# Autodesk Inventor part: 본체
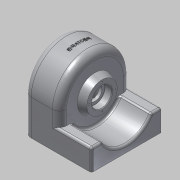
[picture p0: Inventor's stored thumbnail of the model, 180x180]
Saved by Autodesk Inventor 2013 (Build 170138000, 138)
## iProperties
Created: 2015-02
Part Number: 본체
Material: 알루미늄 6061
Document SubType Name: Modeling
Designer: Administrator
Density: 1 g/cm^3
Author: Administrator
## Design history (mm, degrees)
sketch "스케치1"
  geometry: L1 (-50, -25)-(50, -25); L2 (50, -25)-(50, 25); L3 (50, 25)-(-50, 25); L4 (-50, 25)-(-50, -25); L5 (-50, -25)-(50, 25); L6 (50, -25)-(-50, 25); A1 r 50 centre (0, 25) between (50, 25) and (-50, 25); 1 further point
  constraints: 12 end point, 3 midpoint, 2 parallel, 2 point on circle, 1 centre point, 1 horizontal, 1 perpendicular
  dimensions: "d0" = 100 distance of L1.start L1.end; "d2" = 50 distance of L3.end L1.start
extrude "돌출2" new body sketch "스케치1" distance "d7" = 50; taper "d8" = 0 deg
sketch "스케치3"
  geometry: L1 (-25, -50)-(25, -50) reference; L2 (25, -50)-(25, 50) reference; L3 (25, 50)-(-25, 50) reference; L4 (25, -50)-(-5, -50); L5 (-5, -50)-(-5, -34.641); L6 (25, 50)-(-5, 50); L7 (-5, 50)-(-5, 34.641); L8 (25, -50)-(25, 50); A1 r 50 centre (-25, 0) between (-25, 50) and (-25, -50) reference; A2 r 40 centre (-25, 0) between (-5, -34.641) and (-5, 34.641); 1 further point
  constraints: 10 end point, 2 perpendicular, 2 point on circle, 2 point on line, 1 centre point, 1 coincident, 1 collinear
  dimensions: "d9" = 80 diameter of A2; "d10" = 30 distance of L1.end L4.end; "d11" = 30 distance of L2.end L6.end
extrude "돌출3" join sketch "스케치3" distance "d12" = 45; taper "d13" = 0 deg
sketch "스케치5"
  geometry: C1 r 20 at (25, 0); A1 r 50 centre (25, 0) between (25, -50) and (25, 50) reference; 1 further point
  constraints: 1 centre point, 1 coincident
  dimensions: "d14" = 40 diameter of C1
extrude "돌출4" join sketch "스케치5" distance "d15" = 9; taper "d16" = 0 deg
node "작업 평면1"
sketch "스케치6"
  geometry: L1 (50, -50)-(50, 0) reference; L2 (50, 0)-(50, 20) reference; L3 (50, 20)-(50, 40) reference; L4 (50, 0)-(60, 0); L5 (50, 0)-(50, -25); L6 (50, -25)-(60, -21.36); L7 (60, -21.36)-(60, 0); 1 further point
  constraints: 8 end point, 1 midpoint, 1 parallel, 1 perpendicular
  dimensions: "d17" = 10 distance of L1.end L4.end; "d18" = 25 distance of L1.end L5.end; "d19" = 110 deg angle of L1 L6
revolve "회전1" sketch "스케치6" stored, may be unused: angle "d20" = 90 deg
sketch "스케치7"
  geometry: L1 (0, 0)-(0, 100) reference; L2 (0, 100)-(-95, 100) reference; L3 (-46, 96)-(-4, 96); L4 (-4, 96)-(-4, 4); L5 (-4, 4)-(-46, 4); L6 (-46, 4)-(-46, 96); 1 further point
  constraints: 8 end point, 2 parallel, 1 horizontal, 1 perpendicular
  dimensions: "d21" = 42 distance of L3.start L3.end; "d23" = 92 distance between parallel lines of L5 L3; "d24" = 4 distance between parallel lines of L3 L2; "d25" = 4 distance between parallel lines of L1 L4
extrude "돌출5" cut sketch "스케치7" distance "d26" = 50; taper "d27" = 0 deg
node "작업 평면2"
sketch "스케치9"
  geometry: L1 (25, -46)-(25, 46) reference; L2 (25, 46)-(25, -46); A1 r 46 centre (25, 0) between (25, -46) and (25, 46); A2 r 50 centre (25, 0) between (25, -50) and (25, 50) reference; 1 further point
  constraints: 2 end point, 2 point on circle, 1 centre point, 1 collinear, 1 midpoint
extrude "돌출6" cut sketch "스케치9" stored distance "d29" = 42; taper "d30" = 0 deg
sketch "스케치10"
  geometry: C1 r 21.36 at (0, 0) reference; 2 further points
  constraints: 1 coincident
hole "구멍1" sketch "스케치10" at (0, 0) diameter "d31" = 20; stored, may be unused: countersink angle "d35" = 90 deg, drill point angle "d37" = 0 deg; dims "d32" = 6, "d33" = 28, "d34" = 10, "d36" = 4
sketch "스케치11"
  geometry: L1 (0, 0)-(-18, 0); C1 r 14 at (0, 0) reference; C2 r 21.36 at (0, 0) reference; 5 further points
  constraints: 2 end point, 1 coincident, 1 horizontal, 5 other
  dimensions: "d38" = 18 distance of L1.start L1.end; "d41" = 360 deg dimension on C1.centre point (-18, 0) (derived)
hole "구멍2" sketch "스케치11" at (0, 18), (18, 0), (0, -18), (-18, 0) diameter "d43" = 2.459; stored, may be unused: countersink angle "d47" = 90 deg, drill point angle "d49" = 118 deg; dims "d44" = 6, "d45" = 28, "d46" = 10, "d48" = 9
sketch "스케치13"
  geometry: L1 (4, 0)-(4, -46) reference; L2 (4, 0)-(-6, 0); L3 (-6, 0)-(-6, -10); L4 (-6, -10)-(-4, -10); L5 (-4, -10)-(-4, -14); L6 (-4, -14)-(4, -14); L7 (4, -14)-(4, 0); 1 further point
  constraints: 12 end point, 4 perpendicular, 1 collinear, 1 parallel, 1 point on line
  dimensions: "d50" = 10 distance of L1.start L2.end; "d51" = 10 distance of L2.end L3.end; "d52" = 2 distance of L3.end L4.end; "d53" = 4 distance of L4.end L5.end
revolve "회전2" sketch "스케치13" stored, may be unused: angle "d54" = 90 deg
sketch "스케치14"
  geometry: L1 (0, 100)-(-95, 100) reference; L2 (-95, 0)-(-95, 100) reference; 5 further points
  constraints: 2 horizontal alignment, 2 vertical alignment
  dimensions: "d55" = 33 distance of point (-53, 91.75) point (-86, 91.75); "d57" = 83.5 distance of point (-86, 91.75) point (-86, 8.25); "d58" = 9 distance from line of L2 point (-86, 91.75); "d59" = 8.25 distance from line of L1 point (-86, 91.75)
hole "구멍3" sketch "스케치14" at (-86, 8.25), (-86, 91.75), (-53, 91.75), (-53, 8.25) diameter "d60" = 5.134; stored, may be unused: countersink angle "d64" = 90 deg, drill point angle "d66" = 118 deg; dims "d61" = 10, "d62" = 4, "d63" = 2, "d65" = 13
node "작업 평면3"
sketch "스케치15"
  geometry: 2 further points
  constraints: 1 other
feature "엠보싱1" sketch "스케치15" dims "d0" = 100, "d2" = 50, "d67" = 0.5, "d68" = 0
fillet "모깎기1" dims "d69" = 10
fillet "모깎기2" dims "d70" = 6
fillet "모깎기3" dims "d71" = 3
fillet "모깎기4" dims "d72" = 3
chamfer "모따기1" distance "d73" = 1; stored, may be unused: second distance "d74" = 2, angle "d75" = 45 deg
fillet "모깎기5" dims "d76" = 0.3
fillet "모깎기6" dims "d77" = 3
fillet "모깎기7" dims "d78" = 0.3
node "솔리드2"
